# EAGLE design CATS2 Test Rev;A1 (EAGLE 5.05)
MFG: Tyco; SOCKET_MFG: Mill-Max Mfg

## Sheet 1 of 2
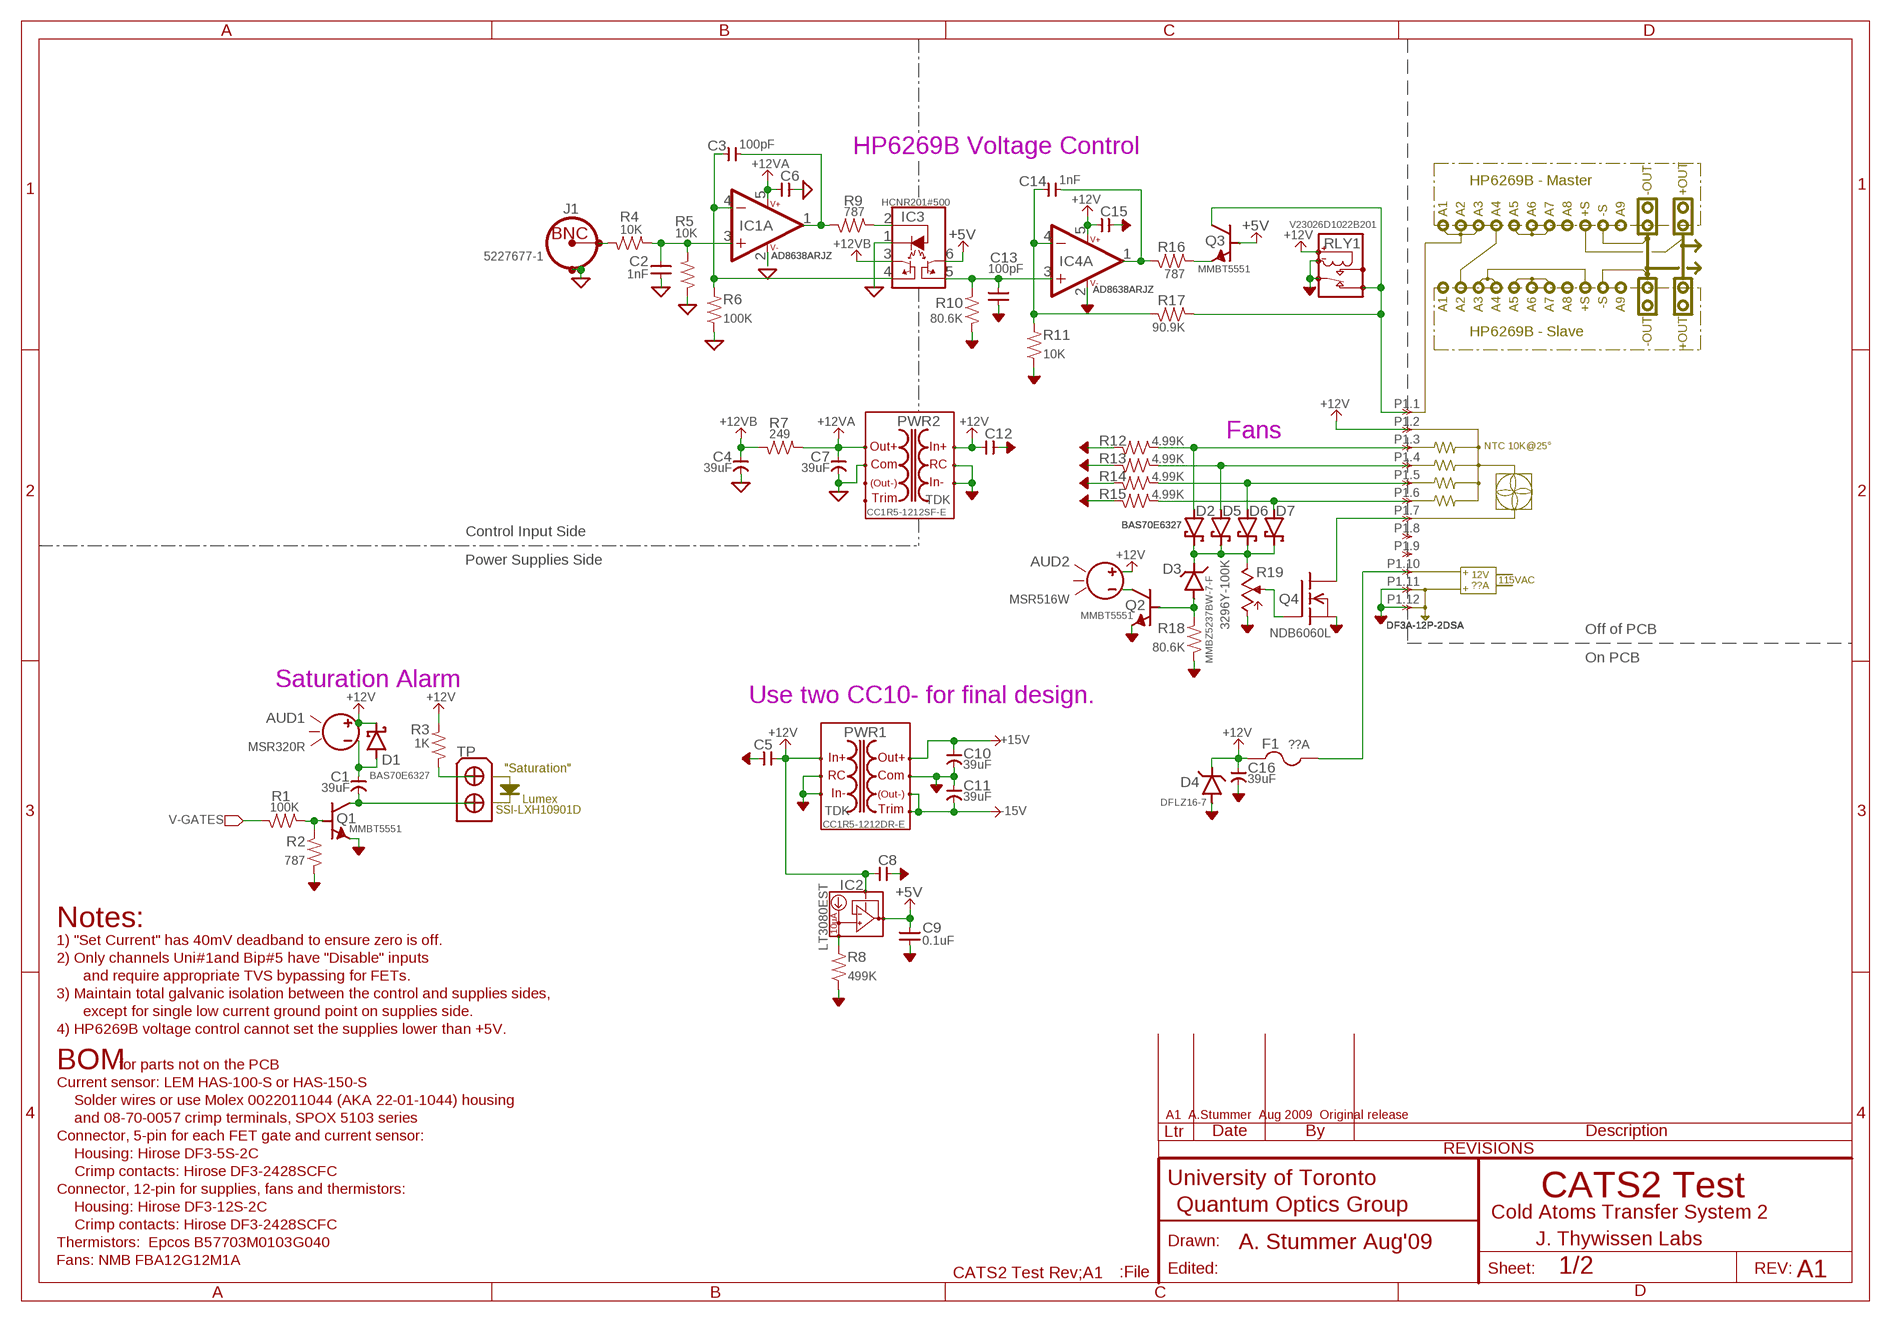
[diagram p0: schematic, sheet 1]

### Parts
AUD1  MSR320R  AUDIO_DEVICE1-MALLORY_MSR  [MALLORY_MSR]
AUD2  MSR516W  AUDIO_DEVICE1-MALLORY_MSR  [MALLORY_MSR]
C1  39uF  CAP-POL--NIPPONCHEM_E61  [CAP:NIPPONCHEM_E61]
C2  1nF  CAP-V-0805  [2012(0805)]
C3  100pF  CAP-H-0805  [2012(0805)]
C4  39uF  CAP-POL--NIPPONCHEM_E61  [CAP:NIPPONCHEM_E61]
C5  0.1uF  CAP-H-0805  [2012(0805)]
C6  0.1uF  CAP-H-0805  [2012(0805)]
C7  39uF  CAP-POL--NIPPONCHEM_E61  [CAP:NIPPONCHEM_E61]
C8  0.1uF  CAP-H-0805  [2012(0805)]
C9  0.1uF  CAP-V-0805  [2012(0805)]
C10  39uF  CAP-POL--NIPPONCHEM_E61  [CAP:NIPPONCHEM_E61]
C11  39uF  CAP-POL--NIPPONCHEM_E61  [CAP:NIPPONCHEM_E61]
C12  0.1uF  CAP-H-0805  [2012(0805)]
C13  100pF  CAP-V-0805  [2012(0805)]
C14  1nF  CAP-H-0805  [2012(0805)]
C15  0.1uF  CAP-H-0805  [2012(0805)]
C16  39uF  CAP-POL--NIPPONCHEM_E61  [CAP:NIPPONCHEM_E61]
D1  BAS70E6327  DIODE,SCHOTTKY-SOT-23  [SOT23]
D2  BAS70E6327  DIODE,SCHOTTKY-SOT-23  [SOT23]
D3  MMBZ5237BW-7-F  ZENER-SOT23  [SOT23]
D4  DFLZ16-7  ZENER-DFLZ  [ZENER:DFLZ_V_(1W)]
D5  BAS70E6327  DIODE,SCHOTTKY-SOT-23  [SOT23]
D6  BAS70E6327  DIODE,SCHOTTKY-SOT-23  [SOT23]
D7  BAS70E6327  DIODE,SCHOTTKY-SOT-23  [SOT23]
F1  ??A  FUSE-5X20-4  [FUSE]
IC1  AD8638ARJZ  OPAMP-SOT23-5  [SOT23-5]
IC2  LT3080EST  REGULATOR:LT3080(3PIN,LDO,I-SET)-SOT223  [SOT223(C)]
IC3  HCNR201#500  OPTO:LINEAR-TYPE1AVAGO#300  [SMD:AVAGO#300(8PIN)]
IC4  AD8638ARJZ  OPAMP-SOT23-5  [SOT23-5]
J1  5227677-1  CONN-BNCTYPE3HORIZ  [CONN-BNC-AMP-TYPE3HORIZ]
P1  DF3A-12P-2DSA  CONN-1X12-TYPE1  [CONN-1X12-TYPE1]
PWR1  CC1R5-1212DR-E  DC-DC:CCP-__-E(TDK1.5-25W)-CC1R5-R-E  [DC-DC:CC1R5-XXXXX-R-E(TDK/LAMBDA)]
PWR2  CC1R5-1212SF-E  DC-DC:CCP-__-E(TDK1.5-25W)-CC1R5-R-E  [DC-DC:CC1R5-XXXXX-R-E(TDK/LAMBDA)]
Q1  MMBT5551  BJT-NPN-SOT23  [SOT23]
Q2  MMBT5551  BJT-NPN-SOT23  [SOT23]
Q3  MMBT5551  BJT-NPN-SOT23  [SOT23]
Q4  NDB6060L  FET-N:NDB6060L(6A,48V,LOGIC)  [TO263]
R1  100K  R-H-0805  [2012(0805)]
R2  787  R-V-0805  [2012(0805)]
R3  1K  R-V-0805  [2012(0805)]
R4  10K  R-H-0805  [2012(0805)]
R5  10K  R-V-0805  [2012(0805)]
R6  100K  R-V-0805  [2012(0805)]
R7  249  R-H-0805  [2012(0805)]
R8  499K  R-V-0805  [2012(0805)]
R9  787  R-H-0805  [2012(0805)]
R10  80.6K  R-V-0805  [2012(0805)]
R11  10K  R-V-0805  [2012(0805)]
R12  4.99K  R-H-0805  [2012(0805)]
R13  4.99K  R-H-0805  [2012(0805)]
R14  4.99K  R-H-0805  [2012(0805)]
R15  4.99K  R-H-0805  [2012(0805)]
R16  787  R-H-0805  [2012(0805)]
R17  90.9K  R-H-0805  [2012(0805)]
R18  80.6K  R-V-0805  [2012(0805)]
R19  3296Y-100K  POT-BOURNS_3296Y  [BOURNS-3296Y]
RLY1  V23026D1022B201  RELAY:SPDT-TYCO_V23026(SMT)  [RELAY:SPDT-TYCO_V23026]
TP  CONN-TP2-1X2  [JUMPER-1X2]

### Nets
+5V: C9.2 IC2.2(OUT) IC3.6(VCC2) Q3.1(B) ; also sheet 2
+12V: AUD1.+ AUD2.+ C5.1 C8.1 C12.1 C15.1 C16.POS D1.3(C) D4.C F1.1A IC2.3(IN) IC4.5(B:V++) P1.2 PWR1.+VIN(+IN) PWR2.+VIN(+IN) R3.2 RLY1.COIL+ ; also sheet 2
+12VA: C6.1 C7.POS IC1.5(B:V++) PWR2.+VOUT(+OUT) R7.1 ; also sheet 2
+12VB: C4.POS IC3.3(VCC1) R7.2 ; also sheet 2
+15V: C10.POS PWR1.+VOUT(+OUT) ; also sheet 2
-15V: C11.NEG PWR1.-VOUT(-OUT) PWR1.TRM(TRIM) ; also sheet 2
AGND: C5.2 C8.2 C9.1 C10.NEG C11.POS C12.2 C13.1 C15.2 C16.NEG D4.A IC4.2(B:V-) P1.11 P1.12 PWR1.-VIN(-IN) PWR1.COM PWR1.RC PWR2.-VIN(-IN) PWR2.RC Q1.2(E) Q2.2(E) Q4.3(S) R2.1 R8.1 R10.1 R11.1 R12.2 R13.2 R14.2 R15.2 R18.1 R19.CCW RLY1.COIL- RLY1.COM ; also sheet 2
GND: C2.1 C4.NEG C6.2 C7.NEG IC1.2(B:V-) IC3.1(LED-) J1.SHIELD1 J1.SHIELD2 PWR2.COM R5.1 R6.1 ; also sheet 2
N$1: Q3.2(E) R16.1
N$2: C14.2 IC4.1(A:OUT) R16.2
N$4: C14.1 IC4.4(A:-IN) R11.2 R17.2
N$19: R3.1 TP.1
N$20: P1.1 Q3.3(C) R17.1 RLY1.NC
N$24: Q1.1(B) R1.1 R2.2
N$27: C1.NEG Q1.3(C) TP.2
N$28: AUD1.- C1.POS D1.1(A)
N$29: D3.1(A) Q2.1(B) R18.2
N$30: IC2.1(SET) R8.2
N$31: F1.2A P1.10
N$32: P1.7 Q4.2(D)
N$33: D7.1(A) P1.6 R15.1
N$34: D6.1(A) P1.5 R14.1
N$35: D5.1(A) P1.4 R13.1
N$36: D2.1(A) P1.3 R12.1
N$37: D2.3(C) D3.3(C) D5.3(C) D6.3(C) D7.3(C) R19.CW
N$38: Q4.1(G) R19.W
N$41: AUD2.- Q2.3(C)
N$49: C13.2 IC3.5(I2) IC4.3(A:+IN) R10.2
N$50: C3.2 IC1.1(A:OUT) R9.2
N$51: IC3.2(LED+) R9.1
N$52: J1.CONDUCTOR R4.2
N$53: C2.2 IC1.3(A:+IN) R4.1 R5.2
N$54: C3.1 IC1.4(A:-IN) IC3.4(I1) R6.2
V-GATES: R1.2 ; also sheet 2
Unconnected: P1.8 P1.9 PWR2.-VOUT(-OUT) PWR2.TRM(TRIM) RLY1.NO

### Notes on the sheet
- HP6269B Voltage Control
- HP6269B - Master
- -OUT | +OUT
- A1 | A2 | A3 | A4 | A5 | A6 | A7 | A8 | +S | -S | A9
- A1 | A2 | A3 | A4 | A5 | A6 | A7 | A8 | +S | -S | A9
- -OUT | +OUT
- HP6269B - Slave
- Fans
- NTC 10K@25°
- Control Input Side
- Power Supplies Side
- + | 12V
- 115VAC
- ??A
- +
- Off of PCB
- On PCB
- Saturation Alarm
- Use two CC10- for final design.
- "Saturation"
- Lumex
- SSI-LXH10901D
- Notes:
- 1) "Set Current" has 40mV deadband to ensure zero is off.
- 2) Only channels Uni#1and Bip#5 have "Disable" inputs
- and require appropriate TVS bypassing for FETs.
- 3) Maintain total galvanic isolation between the control and supplies sides,
- except for single low current ground point on supplies side.
- 4) HP6269B voltage control cannot set the supplies lower than +5V.
- BOM | for parts not on the PCB
- Current sensor: LEM HAS-100-S or HAS-150-S
- Solder wires or use Molex 0022011044 (AKA 22-01-1044) housing
- A1  A.Stummer  Aug 2009  Original release
- and 08-70-0057 crimp terminals, SPOX 5103 series
- Connector, 5-pin for each FET gate and current sensor:
- Housing: Hirose DF3-5S-2C
- Crimp contacts: Hirose DF3-2428SCFC
- Connector, 12-pin for supplies, fans and thermistors: | CATS2 Test
- Housing: Hirose DF3-12S-2C
- Cold Atoms Transfer System 2
- Crimp contacts: Hirose DF3-2428SCFC
- Thermistors:  Epcos B57703M0103G040 | A. Stummer Aug'09 | J. Thywissen Labs
- Fans: NMB FBA12G12M1A
- A1

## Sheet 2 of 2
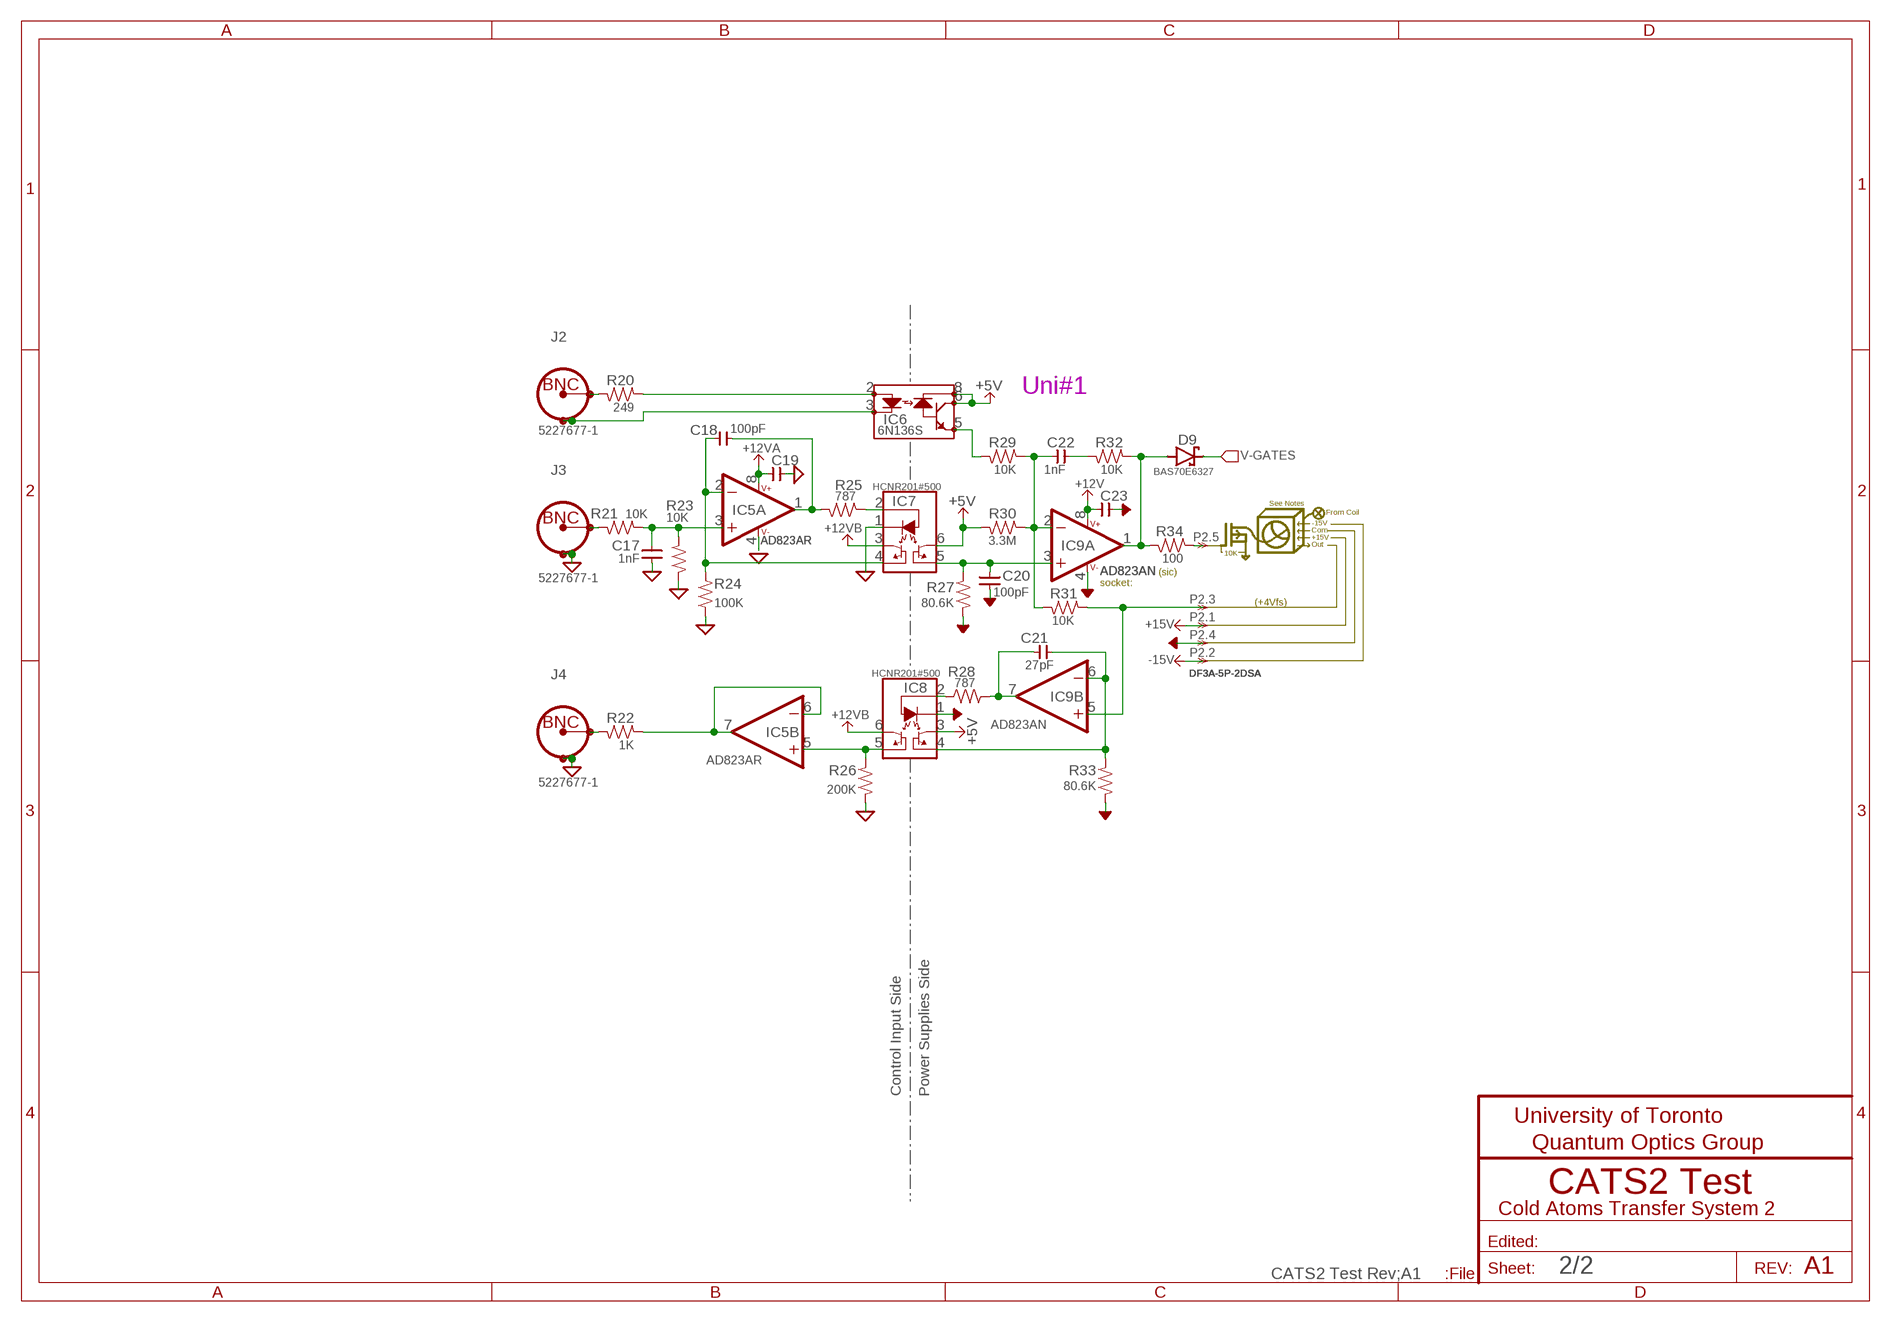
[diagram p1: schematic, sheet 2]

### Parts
C17  1nF  CAP-V-0805  [2012(0805)]
C18  100pF  CAP-H-0805  [2012(0805)]
C19  0.1uF  CAP-H-0805  [2012(0805)]
C20  100pF  CAP-V-0805  [2012(0805)]
C21  27pF  CAP-H-0805  [2012(0805)]
C22  1nF  CAP-H-0805  [2012(0805)]
C23  0.1uF  CAP-H-0805  [2012(0805)]
D9  BAS70E6327  DIODE,SCHOTTKY-SOT-23  [SOT23]
IC5  AD823AR  OPAMP:AD8___(DUAL)-SOIC-8  [SOIC-8]
IC6  6N136S  OPTO:6N136-S  [SMD:6N13X(8PIN)]
IC7  HCNR201#500  OPTO:LINEAR-TYPE1AVAGO#300  [SMD:AVAGO#300(8PIN)]
IC8  HCNR201#500  OPTO:LINEAR-TYPE1AVAGO#300  [SMD:AVAGO#300(8PIN)]
IC9  AD823AN  OPAMP:AD8___(DUAL)-DIP8  [DIL08]
J2  5227677-1  CONN-BNCTYPE3HORIZ  [CONN-BNC-AMP-TYPE3HORIZ]
J3  5227677-1  CONN-BNCTYPE3HORIZ  [CONN-BNC-AMP-TYPE3HORIZ]
J4  5227677-1  CONN-BNCTYPE3HORIZ  [CONN-BNC-AMP-TYPE3HORIZ]
P2  DF3A-5P-2DSA  CONN-1X5-TYPE1  [CONN-1X5-TYPE1]
R20  249  R-H-0805  [2012(0805)]
R21  10K  R-H-0805  [2012(0805)]
R22  1K  R-H-0805  [2012(0805)]
R23  10K  R-V-0805  [2012(0805)]
R24  100K  R-V-0805  [2012(0805)]
R25  787  R-H-0805  [2012(0805)]
R26  200K  R-V-0805  [2012(0805)]
R27  80.6K  R-V-0805  [2012(0805)]
R28  787  R-H-0805  [2012(0805)]
R29  10K  R-H-0805  [2012(0805)]
R30  3.3M  R-H-0805  [2012(0805)]
R31  10K  R-H-0805  [2012(0805)]
R32  10K  R-H-0805  [2012(0805)]
R33  80.6K  R-V-0805  [2012(0805)]
R34  100  R-H-0805  [2012(0805)]

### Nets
+5V: IC6.6(OUT) IC6.8(VDD) IC7.6(VCC2) IC8.3(VCC1) R30.2 ; also sheet 1
+12V: C23.1 IC9.8(PWR:V++) ; also sheet 1
+12VA: C19.1 IC5.8(PWR:V++) ; also sheet 1
+12VB: IC7.3(VCC1) IC8.6(VCC2) ; also sheet 1
+15V: P2.1 ; also sheet 1
-15V: P2.2 ; also sheet 1
AGND: C20.1 C23.2 IC8.1(LED-) IC9.4(PWR:V-) P2.4 R27.1 R33.1 ; also sheet 1
GND: C17.1 C19.2 IC5.4(PWR:V-) IC7.1(LED-) J3.SHIELD1 J3.SHIELD2 J4.SHIELD1 J4.SHIELD2 R23.1 R24.1 R26.1 ; also sheet 1
N$43: P2.5 R34.1
N$44: D9.1(A) IC9.1(A:OUT) R32.1 R34.2
N$45: C22.1 IC9.2(A:-IN) R29.1 R30.1 R31.2
N$46: IC9.5(B:+IN) P2.3 R31.1
N$47: C22.2 R32.2
N$48: C20.2 IC7.5(I2) IC9.3(A:+IN) R27.2
N$55: C18.2 IC5.1(A:OUT) R25.2
N$56: IC7.2(LED+) R25.1
N$57: J3.CONDUCTOR R21.2
N$58: C17.2 IC5.3(A:+IN) R21.1 R23.2
N$59: C18.1 IC5.2(A:-IN) IC7.4(I1) R24.2
N$61: C21.2 IC9.7(B:OUT) R28.2
N$62: IC8.2(LED+) R28.1
N$63: C21.1 IC8.4(I1) IC9.6(B:-IN) R33.2
N$64: IC5.5(B:+IN) IC8.5(I2) R26.2
N$65: IC5.6(B:-IN) IC5.7(B:OUT) R22.1
N$66: J4.CONDUCTOR R22.2
N$67: J2.CONDUCTOR R20.2
N$68: IC6.2(ANODE) R20.1
N$69: IC6.3(CATHODE) J2.SHIELD1 J2.SHIELD2
N$71: IC6.5(COM) R29.2
V-GATES: D9.3(C) ; also sheet 1

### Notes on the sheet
- Uni#1
- See Notes
- From Coil
- -15V
- Com
- +15V
- Out
- 10K
- (sic)
- socket:
- (+4Vfs)
- Control Input Side | Power Supplies Side
- CATS2 Test
- Cold Atoms Transfer System 2
- A1

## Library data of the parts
AUD1 AUD2 = QuantumOptics:AUDIO_DEVICE1: Audio Warning Device, Mallory MSR series, through hole, various sounds.
C1 C4 C7 C10 C11 C16 = QuantumOptics:CAP-POL-: Capacitor, Polarized, SMT 0805 and up, probably tantalum.
C2 C9 C13 C17 C20 = QuantumOptics:CAP-V-: Cap, SMT and Through-hole, 0402 and up.
C3 C5 C6 C8 C12 C14 C15 C18 C19 C21-C23 = QuantumOptics:CAP-H-: Cap, SMT and Through-hole, 0402 and up.
D1 D2 D5-D7 D9 = QuantumOptics:DIODE,SCHOTTKY: Schottky Diode, general purpose.
D3 D4 = QuantumOptics:ZENER: Zener
F1 = QuantumOptics:FUSE: Fuse
IC1 IC4 = QuantumOptics:OPAMP: Op Amp, generic, pick the right package. e.g. AD8605: SOT-23-5, RRIO, 10MHz, Ib = 1pA, Vio < 65uV, 2.7-5.5V.
IC2 = QuantumOptics:REGULATOR:LT3080(3PIN,LDO,I-SET): LT3080, LDO, output set by single resistor, nice part, LinTech, 1A, SOT223, MSOP8, TO220. http://cds.linear.com/docs/Datasheet/3080f.pdf
IC3 IC7 IC8 = QuantumOptics:OPTO:LINEAR-TYPE1: Linear opto-coupler, Avago HCNR20x or Clare LOC11x Best: http://www.avagotech.com/docs/AV02-0886EN Okay: http://www.clare.com/home/pdfs.nsf/www/LOC110.pdf/$file/LOC110.pdf
IC5 IC9 = QuantumOptics:OPAMP:AD8___(DUAL): AD8xxx, Analog Devices, dual opamp in SOIC-8 and MSOP-8, various versions available. AD8066, AD8656, etc. e.g. http://www.analog.com/UploadedFiles/Data_Sheets/476080131AD8655_6_a.pdf
IC6 = QuantumOptics:OPTO:6N136: 6N136 optocoupler, Fairchild et al, 1Mbps CTR=27%typ, http://www.fairchildsemi.com/ds/6N/6N136.pdf, Can drop-in 6N137 with 10Mbps logic - http://www.fairchildsemi.com/ds/6N/6N137.pdf
J1-J4 = QuantumOptics:CONN-BNC: BNC PCB, horizontal or vertical, e.g. Horiz: Amp (5)227677-1, nut 1-329631-2, shoulder washer 330620. The two shield connections allow the assembly on either side of the board. Vert isolated: 5227222-6, http://catalog.tycoelectronics.com/TE/bin/TE.Connect?C=1&M=BYPN&TCPN=5227222-6&RQPN=5227222-6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
P1 = QuantumOptics:CONN-1X12-TYPE1: Connector, 12-pin, PCB to wires, Hirose DF3A-12P-2DSA, 2mm. Mates with connector DF3-12S-2C and crimp pins DF3-2428SCFC. http://www.hirose.co.jp/cataloge_hp/e54300012.pdf
P2 = QuantumOptics:CONN-1X5-TYPE1: Connector, 4-pin, PCB to wires, Hirose DF3A-4P-2DSA, 2mm. Mates with connector DF3-4S-2C and crimp pins DF3-2428SCFC. http://www.hirose.co.jp/cataloge_hp/e54300012.pdf
PWR1 PWR2 = QuantumOptics:DC-DC:CCP-__-E(TDK1.5-25W): CCp-inoutsc-E, TDK DC-DC isolated, 1.5-25W, uni- or bipolar "p": 1.5, 3, 6, 10, 15, or 25W. "in": Input 05, 12, 24 or 48V. "out": Output 3.3, 5, 12, ±12 (or 24), ±15 (or30V). "s": Polarity single or dual. "c": Case horiz DIP, horiz SMD or vertical SIP. http://www.tdk.co.jp/tefe02/ea335_cc_e.pdf
Q1-Q3 = QuantumOptics:BJT-NPN: NPN BJT, generic, p/n defined by VALUE field. E.g. Fairchild MMBT5551 (abs max 160V, 600mA. hFE>80@10mA.
Q4 = QuantumOptics:FET-N:NDB6060L(6A,48V,LOGIC): NDB6060L, Fairchild et al., logic level, 6A 48V, TO-263. http://www.fairchildsemi.com/ds/ND/NDB6060L.pdf
R1 R4 R7 R9 R12-R17 R20-R22 R25 R28-R32 R34 = QuantumOptics:R-H-*: Resistor, SMT & Through-Hole, horizontal symbol
R2 R3 R5 R6 R8 R10 R11 R18 R23 R24 R26 R27 R33 = QuantumOptics:R-V-*: Resistor, SMT & Through-Hole, vertical symbol
R19 = QuantumOptics:POT: Pot, regular or trimpot
RLY1 = QuantumOptics:RELAY:SPDT: SPDT Relay
TP = QuantumOptics:CONN-TP2: Terminal Block, 2 post, generic two post terminal block.

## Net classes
2 100A: width 6.35 mm, clearance 0.381 mm

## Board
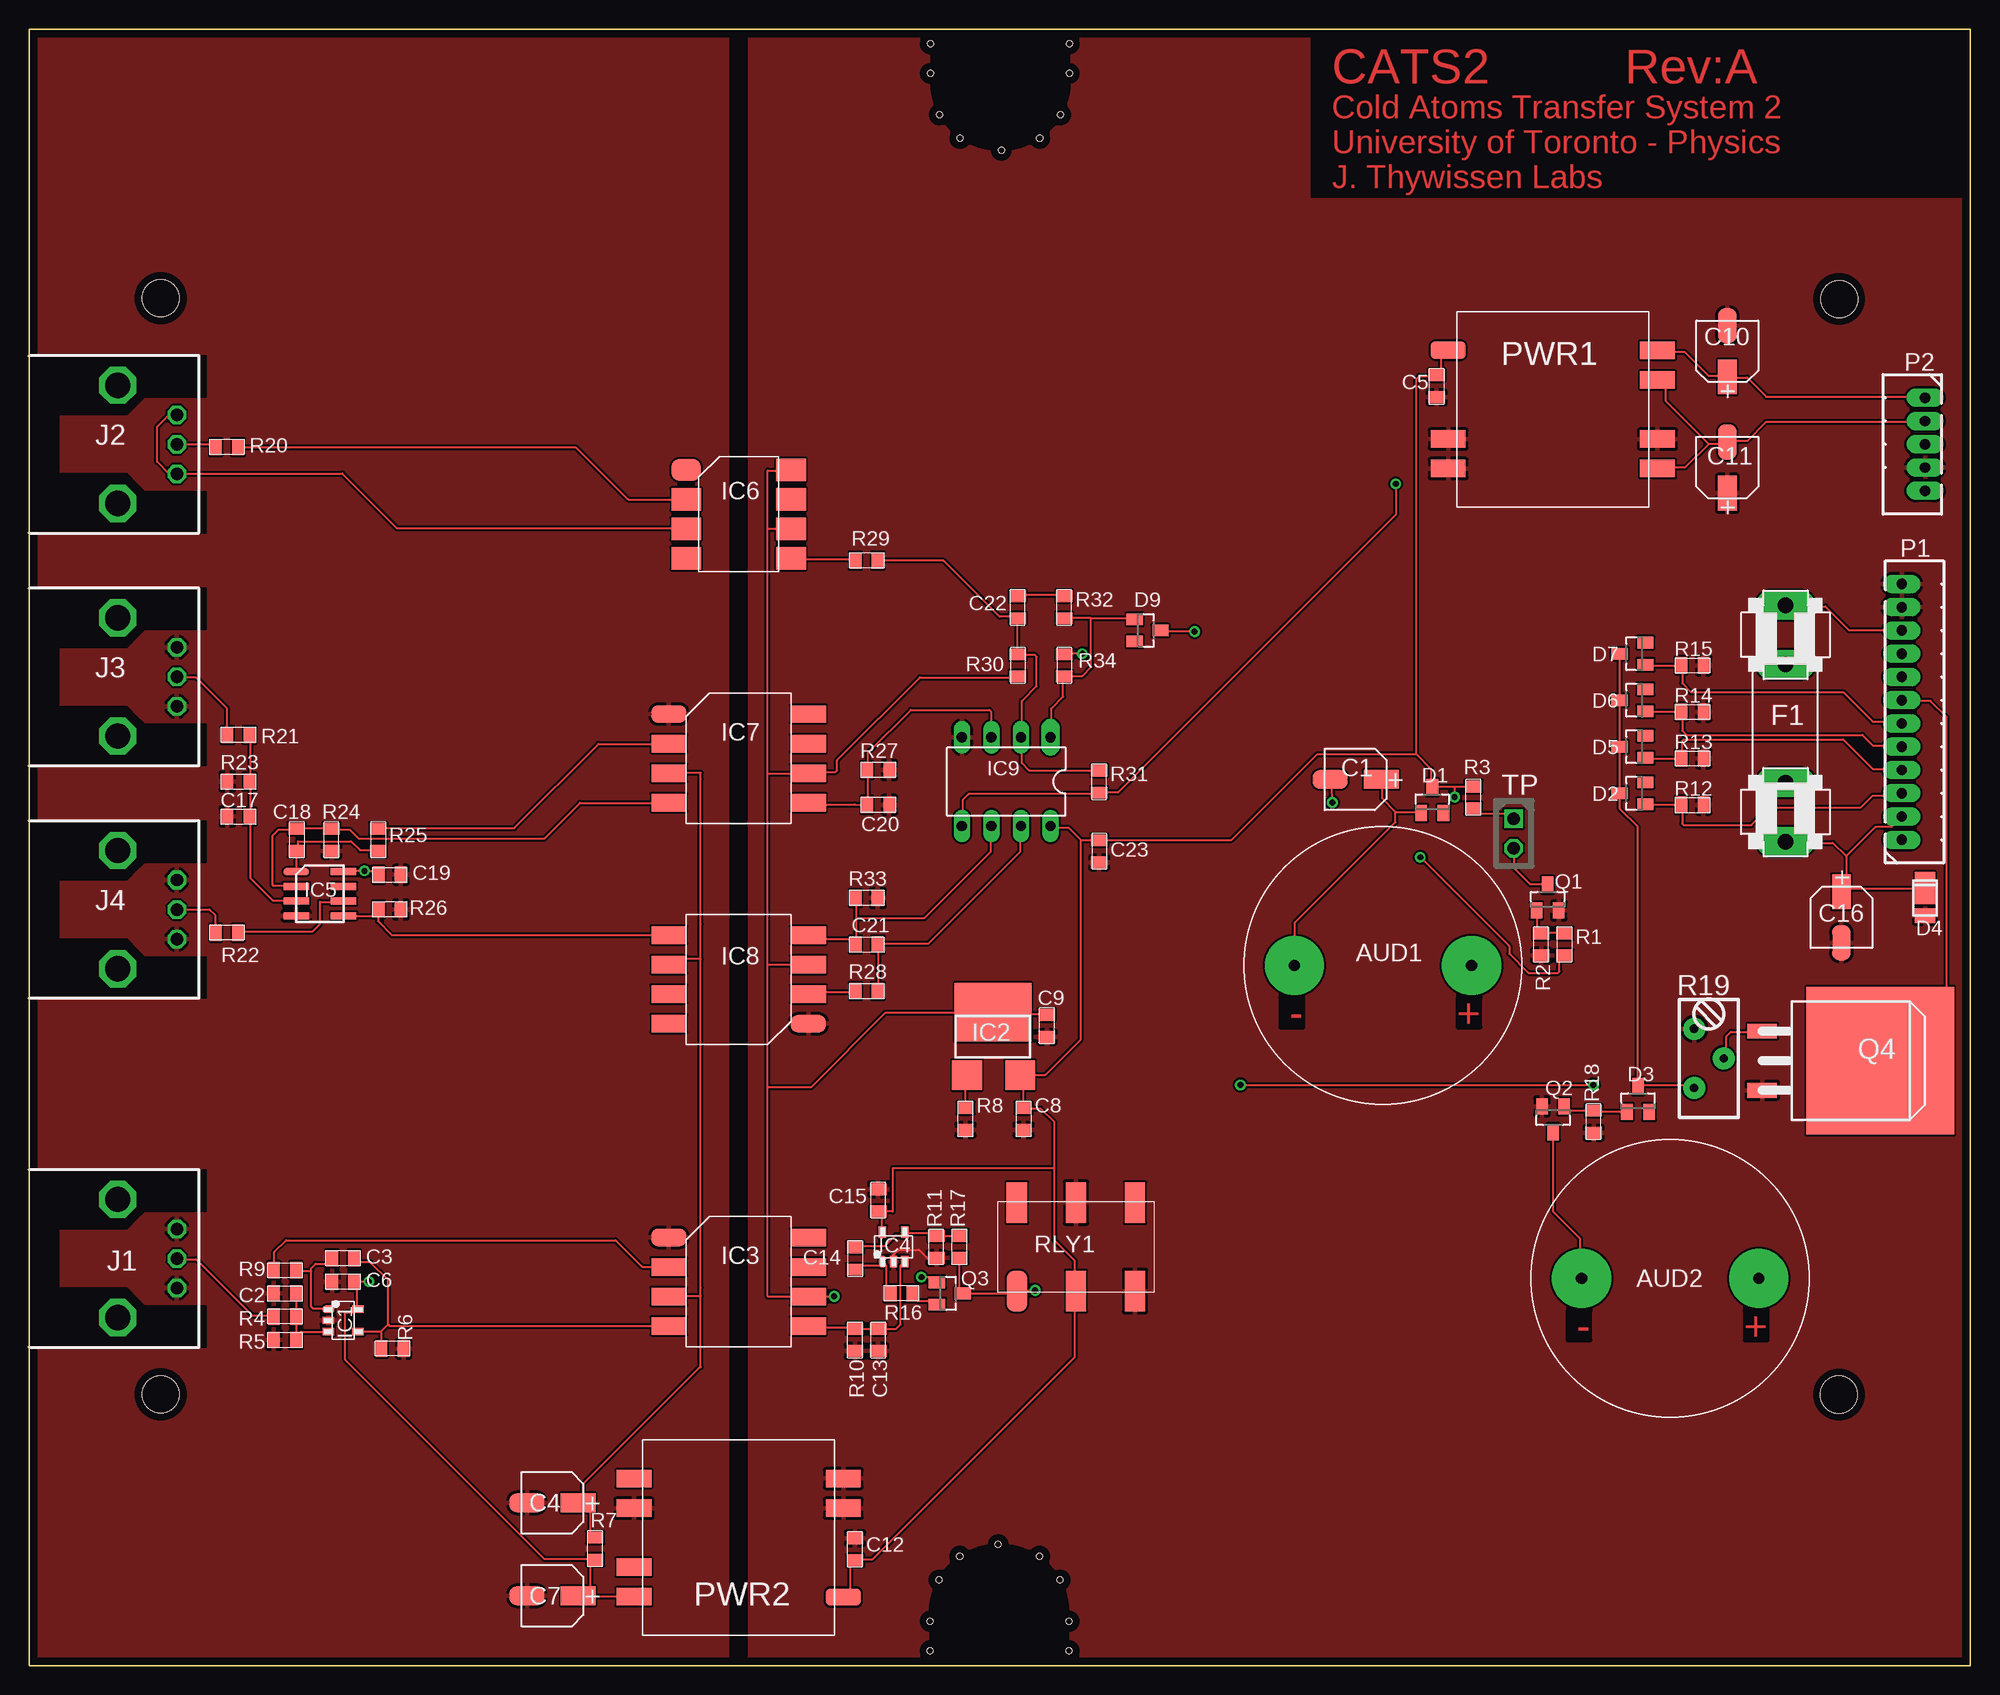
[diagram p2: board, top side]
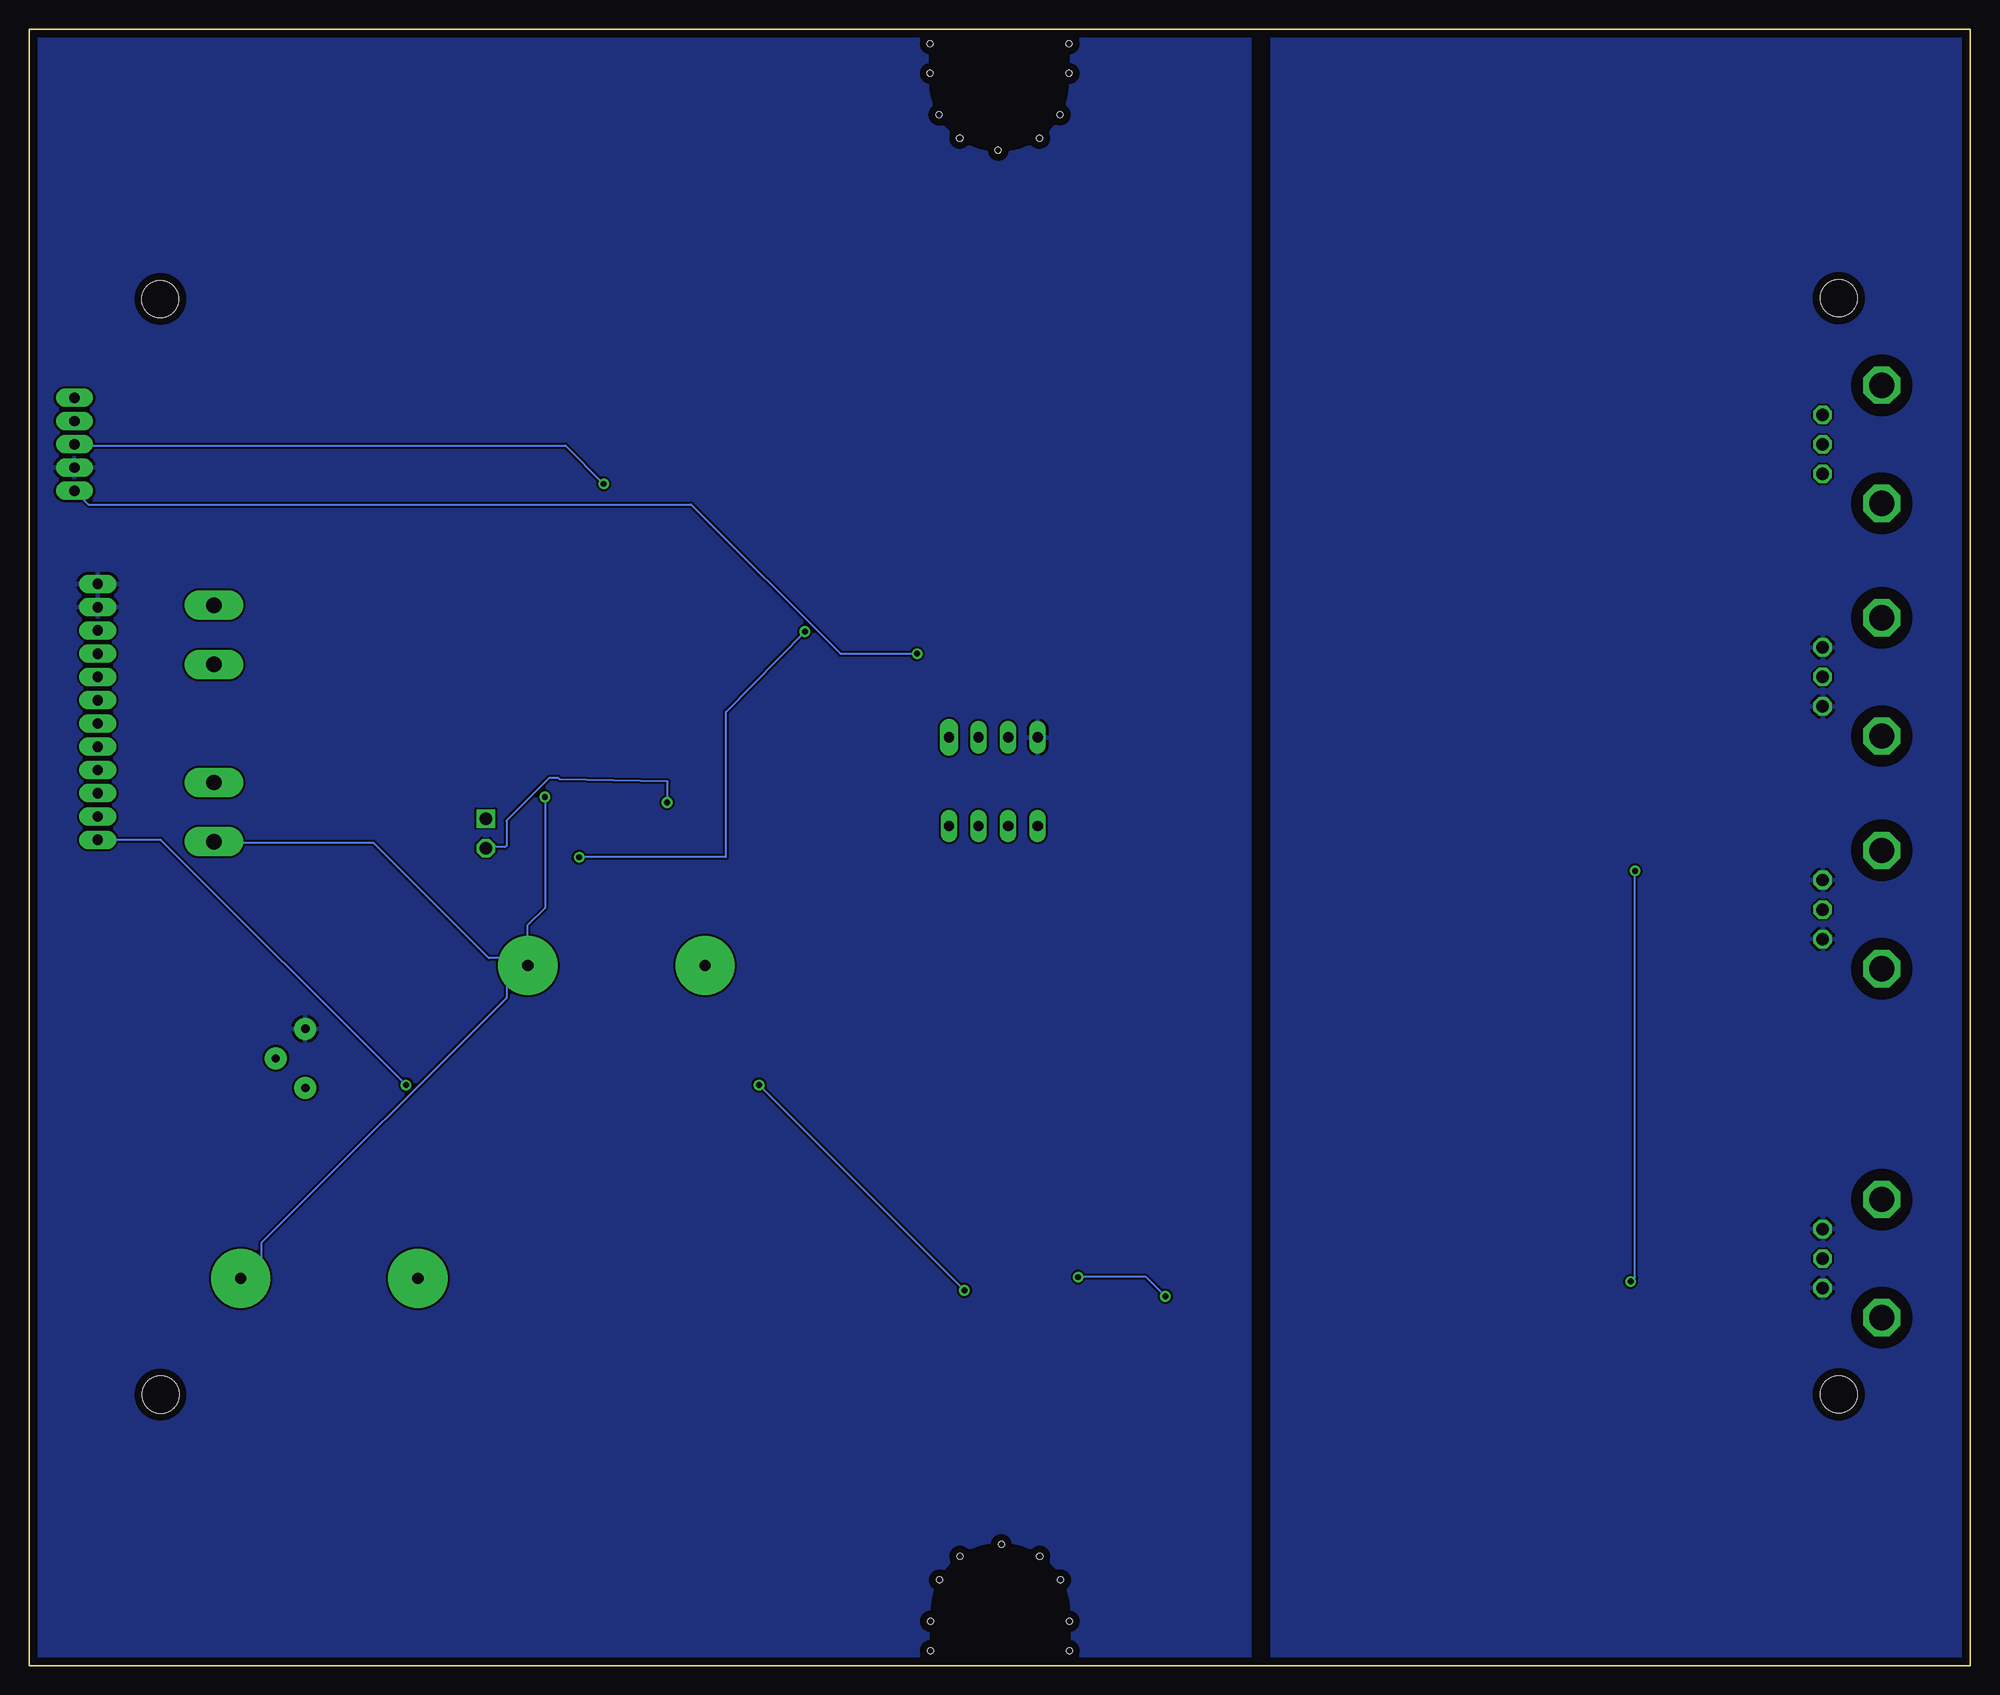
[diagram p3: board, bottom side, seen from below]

Size 166.9 x 140.7 mm. Coordinates in mm from the lower left corner, seen from the top.
Copper layers (1+16): Top 0.035mm / dielectric 1.5mm / Bottom 0.035mm
Design rules "DRC standard check": minimum track width 7mil, minimum drill 20mil, track to track 7mil, track to pad 7mil, pad to pad 7mil, via to via 7mil, smd to smd 0mil, copper to edge 25mil, drill to drill 8mil, minimum pad ring 10mil, minimum via ring 8mil, stop-mask expansion 4mil, vias tented up to drill 0mil, thermal gap 10mil
Holes 3.17 mm at 11.32,117.57 11.32,23.32 155.6,23.3 155.61,117.49

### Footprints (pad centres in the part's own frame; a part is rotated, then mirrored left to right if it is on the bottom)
MALLORY_MSR = drill 0.965 pad 5.08 round: + -7.62,0; - 7.62,0
CAP:NIPPONCHEM_E61 = smd 3 x 1.6: NEG -2.2,0; POS 2.2,0
2012(0805) = smd 1.016 x 1.397: 1 -0.953,0; 2 0.953,0
SOT23 = smd 1 x 1.4: 1 -0.953,-0.953; 2 0.953,-0.953; 3 0,1.27
ZENER:DFLZ_V_(1W) = smd 1.25 x 1.75: A -1.525,0 | smd 2.75 x 1.75: C 0.85,0
FUSE = drill 1.321 pad 2.54 long: 1A -10.16,0; 1B -5.08,0; 2A 10.16,0; 2B 5.08,0
SOT23-5 = smd 0.635 x 0.991: 1 -0.635,-1.27; 2 0.318,-1.27; 3 1.27,-1.27; 4 1.27,1.27; 5 -0.635,1.27
SOT223(C) = smd 2.54 x 2.54: 1 -2.286,-2.54; 3 2.286,-2.54 | smd 6.6 x 5: 2 -0.05,2.87
SMD:AVAGO#300(8PIN) = smd 1.5 x 3: 1 -3.81,-6; 2 -1.27,-6; 3 1.27,-6; 4 3.81,-6; 5 3.81,6; 6 1.27,6; 7 -1.27,6; 8 -3.81,6
SOIC-8 = smd 0.6 x 2.2: 1 -1.27,-2.032; 2 0,-2.032; 3 1.27,-2.032; 4 2.54,-2.032; 5 2.54,2.032; 6 1.27,2.032; 7 0,2.032; 8 -1.27,2.032
SMD:6N13X(8PIN) = smd 1.905 x 2.54: 1 -3.81,-4.508; 2 -1.27,-4.508; 3 1.27,-4.508; 4 3.81,-4.508; 5 3.81,4.508; 6 1.27,4.508; 7 -1.27,4.508; 8 -3.81,4.508
DIL08 = drill 0.889 pad 1.575 long: 1 -3.81,-3.81 | drill 0.889 long: 2 -1.27,-3.81; 3 1.27,-3.81; 4 3.81,-3.81; 5 3.81,3.81; 6 1.27,3.81; 7 -1.27,3.81; 8 -3.81,3.81
CONN-BNC-AMP-TYPE3HORIZ = drill 1.067 octagon: CONDUCTOR 0,-12.7; SHIELD1 -2.54,-12.7; SHIELD2 2.54,-12.7 | drill 2.184 octagon: P$1 -5.08,-7.62; P$2 5.08,-7.62
CONN-1X12-TYPE1 = drill 0.889 pad 1.6 long: 1 3,0; 2 1,0; 3 -1,0; 4 -3,0; 5 -5,0; 6 -7,0; 7 -9,0; 8 -11,0; 9 -13,0; 10 -15,0; 11 -17,0; 12 -19,0
CONN-1X5-TYPE1 = drill 0.889 pad 1.6 long: 1 3,0; 2 1,0; 3 -1,0; 4 -3,0; 5 -5,0
DC-DC:CC1R5-XXXXX-R-E(TDK/LAMBDA) = smd 3 x 1.5: +VIN -9,5.1; +VOUT 9,5.08; -VIN -9,-5.08; -VOUT 9,-5.08; COM 9,-2.54; RC -9,-2.54; TRM 9,2.54
TO263 = smd 1.27 x 2.54: 1 -2.54,0; 3 2.54,0 | smd 12.7 x 12.7: 2 0,10.16
BOURNS-3296Y = drill 0.711 pad 1.905 round: CCW 2.54,1.27; CW -2.54,1.27; W 0,-1.27
RELAY:SPDT-TYCO_V23026 = smd 1.75 x 3.5: 6 5.08,3.81; COIL+ 0,-3.81; COIL- 0,3.81; COM 5.08,-3.81; NC -5.08,-3.81; NO -5.08,3.81
JUMPER-1X2 = drill 1.067 square: 1 0,2.54 | drill 1.067 octagon: 2 0,0
CASE-HAMMOND-1598C = hole 0.508: 77.47,1.27; 77.47,3.81; 78.232,7.366; 80.01,9.398; 83.312,10.414; 86.868,9.398; 88.646,7.366; 89.408,3.81; 89.408,1.27; 89.43,139.43; 89.43,136.89; 88.668,133.334; 86.89,131.302; 83.588,130.286; 80.032,131.302; 78.254,133.334; 77.492,136.89; 77.492,139.43

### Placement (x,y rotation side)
AUD1  116.4,60.2 180 top
AUD2  141.09,33.3 180 top
C1  114.05,76.19 0 top
C2  22,32 0 top
C3  27,35 180 top
C4  45,14 0 top
C5  121,110 270 top
C6  27,33 180 top
C7  45,6 0 top
C8  85.5,47 270 top
C9  87.5,55 90 top
C10  146,113 270 top
C11  146,103 270 top
C12  71,10 90 top
C13  73,28 90 top
C14  71,35 270 top
C15  73,40 90 top
C16  155.81,64.33 90 top
C17  18,73 0 top
C18  23,71 270 top
C19  31,68 0 top
C20  73,74 180 top
C21  72,62 0 top
C22  85,91 90 top
C23  92,70 270 top
D1  120.64,74.25 0 top
D2  138,75 90 top
D3  138.32,48.55 0 top
D4  163,66 90 top
D5  138,79 90 top
D6  138,83 90 top
D7  138,87 90 top
D9  96,89 270 top
F1  151,81 90 top
IC1  27,30 270 top
IC2  82.92,53.31 0 top
IC3  61,33 270 top
IC4  74,36 0 top
IC5  25,67 270 top
IC6  61,99 270 top
IC7  61,78 270 top
IC8  61,59 90 top
IC9  84,76 180 top
J1  0,35 90 top
J2  0,105 90 top
J3  0,85 90 top
J4  0,65 90 top
P1  161,74 270 top
P2  163,106 90 top
PWR1  131,108 0 top
PWR2  61,11 180 top
Q1  130.55,65.87 0 top
Q2  131.02,47.13 180 top
Q3  79,32 270 top
Q4  149,52 270 top
R1  132,62 270 top
R2  130,62 90 top
R3  124.16,74.64 90 top
R4  22,30 180 top
R5  22,28 0 top
R6  31.25,27.25 180 top
R7  48.66,10.06 90 top
R8  80.5,47 90 top
R9  22,34 0 top
R10  71,28 90 top
R11  78,36 90 top
R12  143,74 0 top
R13  143,78 0 top
R14  143,82 0 top
R15  143,86 0 top
R16  75,32 180 top
R17  80,36 90 top
R18  134.51,46.76 90 top
R19  144.42,52.21 90 top
R20  17,104.75 180 top
R21  18,80 180 top
R22  17,63 180 top
R23  18,76 0 top
R24  26,71 90 top
R25  30,71 270 top
R26  31,65 180 top
R27  73,77 180 top
R28  72,58 0 top
R29  72,95 180 top
R30  85,86 270 top
R31  92,76 90 top
R32  89,91 90 top
R33  72,66 180 top
R34  89,86 270 top
RLY1  90,36 0 top
TP  127.63,70.28 0 top
U$7  [CASE-HAMMOND-1598C]  0,0 0 top
U$8  [TITLEBLOCK_PCB]  not placed on the board

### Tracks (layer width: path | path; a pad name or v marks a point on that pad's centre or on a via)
+5V  (via drill 0.51)
  Top 0.178: C9.2 87.38,56.01 83.06,56.01 82.93,56.13 IC2.2 82.8,56.13 | v76.71,33.4 77.6,33.4 77.98,33.02 Q3.1 | v69.22,31.75 67.06,31.75 IC3.6 | IC6.6 65.53,97.79 | 65.53,102.74 IC6.8 | R30.2 84.96,84.96 76.58,84.96 69.47,77.85 69.47,76.96 69.34,76.83 67.06,76.83 IC7.6 66.93,76.71
  Top 0.18: 65.53,102.74 63.5,102.74 63.5,97.75 | 63.5,76.71 66.93,76.71 | 63.5,76.71 63.5,97.75 | 63.5,97.75 65.51,97.75 IC6.6 | 63.5,60.27 IC8.3 | 63.5,60.27 63.5,76.71 | IC3.6 63.5,31.73 63.5,49.75 | 63.5,49.75 63.5,60.27 | 82.8,56.13 73.63,56.13 67.25,49.75 63.5,49.75
  Bottom 0.178: v76.71,33.4 70.87,33.4 v69.22,31.75
+12V  (via drill 0.51)
  Top 0.178: 90.42,70.99 91.95,70.99 C23.1 92.08,70.99 103.38,70.99 110.74,78.36 119.25,78.36 | 90.42,70.99 89.41,72.01 88.01,72.01 87.88,72.14 IC9.8 | PWR2.+VIN 70.1,5.97 70.61,6.48 70.61,8.64 70.99,9.02 C12.1 71.12,9.14 72.52,9.14 89.92,26.54 89.92,32.13 RLY1.COIL+ 89.92,32.26 89.92,34.8 88.14,36.58 88.14,42.75 88.14,46.74 87,47.88 85.6,47.88 C8.1 85.47,48.01 85.47,50.42 85.22,50.67 IC2.3 85.22,50.8 87.38,50.8 90.42,53.85 90.42,70.99 | 156.21,66.8 156.08,66.8 155.83,66.55 C16.POS 156.21,66.8 | 156.21,66.8 162.94,66.8 D4.C | 156.21,69.6 158.75,72.14 160.15,72.14 160.91,72.9 P1.2 | 156.21,69.6 156.21,66.8 | 156.21,69.6 155.07,70.74 151,70.74 F1.1A | PWR1.+VIN 121.92,113.03 121.41,112.52 121.41,111.38 121.03,111 C5.1 120.9,110.87 119.51,110.87 119.25,110.62 119.25,78.36 | 122.56,75.56 120.65,75.56 D1.3 120.52,75.56 120.52,77.09 119.25,78.36 | 122.56,75.56 124.08,75.56 R3.2 | 122.56,75.56 v122.56,74.68 | IC4.5 73.28,37.34 73.28,38.73 73.03,38.99 C15.1
  Top 0.18: 88.14,42.75 74.25,42.75 74.25,39.05 C15.1
  Bottom 0.178: v122.56,74.68 122.56,65.15 124.08,63.63 124.08,60.83 | 124.08,60.83 124.08,60.33 AUD1.+ 124.08,60.83 | 124.08,60.83 125.86,60.83 | 125.86,60.83 127.38,60.83 137.29,70.74 150.88,70.74 F1.1A | 125.86,60.83 125.86,57.4 146.94,36.32 146.94,35.05 148.59,33.4 AUD2.+
+12VA  (via drill 0.51)
  Top 0.178: 52.07,5.97 PWR2.+VOUT 51.94,5.97 47.24,5.97 C7.POS 47.24,6.1 47.62,6.1 48.26,6.73 48.26,8.64 48.64,9.02 R7.1 48.64,9.14 44.32,9.14 27.18,26.29 27.18,30.35 27.81,30.35 28.07,30.61 28.19,30.61 IC1.5 28.19,30.73 28.19,32.77 28.07,32.89 C6.1 28.07,33.02 v29.21,33.02 | C19.1 29.97,68.07 29.72,68.33 v28.83,68.33 27.05,68.33 IC5.8
  Bottom 0.178: v28.83,68.33 28.83,33.4 v29.21,33.02
+12VB
  Top 0.178: 57.75,63.75 57.75,76.25 | 55.12,60.33 IC8.6 | 55.12,76.71 IC7.3 | 47.62,13.97 48.26,13.34 48.26,11.43 48.64,11.05 R7.2 | 47.62,13.97 47.24,13.97 C4.POS 47.62,13.97 | 57.66,25.65 47.62,15.62 47.62,13.97 | 55.12,31.62 IC3.3 | 57.75,32.5 57.75,60.75
  Top 0.18: 55.12,60.33 55.12,60.75 57.75,60.75 57.75,63.75 | 57.75,31.75 57.75,25.65 57.66,25.65 | 57.75,31.75 57.75,32.5 | 55.12,31.62 55.12,31.75 57.75,31.75 | 55.12,76.71 55.12,76.75 57.75,76.75 57.75,76.25
+15V
  Top 0.178: PWR1.+VOUT 140.08,113.03 140.21,112.9 142.37,112.9 144.4,110.87 145.92,110.87 C10.POS 146.05,110.74 147.7,110.74 149.35,109.09 162.94,109.09 P2.1
-15V
  Top 0.178: 144.4,105.03 142.37,103 140.08,103 PWR1.-VOUT | 144.4,105.03 145.8,105.03 145.92,105.16 C11.NEG 146.05,105.28 147.7,105.28 149.35,106.93 162.94,106.93 P2.2 | 144.4,105.03 140.72,108.71 140.72,109.86 140.08,110.49 PWR1.TRM
AGND
  Top 0.18: IC4.2 74.32,35.32 74.75,35.75 76.5,35.75 77.25,35 77.95,35 R11.1
  pour Top: 62,0 167,0 167,126 110,126 110,140 62,140
  pour Bottom: 62,0 167,0 167,140 62,140
GND
  pour Top: 0,140 60,140 60,0 0,0
  pour Bottom: 0,140 60,140 60,0 0,0
N$1
  Top 0.178: R16.1 76.07,31.88 76.07,31.62 76.33,31.37 77.72,31.37 77.98,31.11 Q3.2
N$2
  Top 0.178: 73.66,34.42 73.41,34.67 IC4.1 73.66,34.42 | 73.66,34.42 73.66,32.38 R16.2 | 73.66,34.42 71.63,34.42 71.37,34.16 71.12,34.16 C14.2
N$4
  Top 0.178: 72.93,36.07 71.12,36.07 C14.1 | 75.18,37.21 IC4.4 75.31,37.21 77.72,37.21 77.98,36.96 R11.2 78.11,36.96 79.88,36.96 R17.2
  Top 0.18: 72.93,36.07 73.57,36.07 74.5,37 75,37 IC4.4
N$19
  Top 0.178: R3.1 124.21,73.66 124.59,73.28 127.13,73.28 127.51,72.9 TP.1
N$20  (via drill 0.51)
  Top 0.178: R17.1 80.01,34.92 80.01,32.26 Q3.3 80.39,32 84.71,32 84.84,32.13 RLY1.NC 84.96,32.26 v86.49,32.26 | v104.14,49.91 v134.49,49.91
  Bottom 0.178: v134.49,49.91 155.57,70.99 160.91,70.99 P1.1 | v86.49,32.26 v104.14,49.91
N$24
  Top 0.178: R1.1 131.95,62.99 130.05,62.99 R2.2 129.92,62.99 129.67,63.25 129.67,64.9 Q1.1
N$27  (via drill 0.51)
  Top 0.178: Q1.3 130.43,67.18 129.03,67.18 127.64,68.58 127.64,70.23 TP.2 | v112.05,74.2 111.89,76.2 C1.NEG
  Bottom 0.178: v112.05,74.2 112,74.2 112,76 121.28,76.2 121.41,76.33 122.17,76.33 125.86,72.64 125.86,70.48 125.98,70.36 127.51,70.36 TP.2
N$28
  Top 0.178: 117.47,73.41 119.63,73.41 D1.1 | 117.47,73.41 116.33,74.55 116.33,76.07 C1.POS | 117.47,73.41 117.47,72.52 108.84,63.88 108.84,60.33 AUD1.-
N$29
  Top 0.178: D3.1 137.29,47.62 134.62,47.62 R18.2 134.49,47.75 132.33,47.75 132.08,48.01 Q2.1
N$30
  Top 0.178: R8.2 80.52,48.01 80.52,50.67 IC2.1
N$31
  Top 0.178: P1.10 160.91,89.03 156.46,89.03 154.43,91.06 151,91.06 F1.2A
N$32
  Top 0.178: P1.7 161.04,82.93 163.45,82.93 164.85,81.53 164.85,57.66 159.26,52.07 Q4.2
N$33
  Top 0.178: D7.1 139.06,85.98 141.99,85.98 R15.1 142.11,85.98 142.11,84.45 142.88,83.69 155.96,83.69 158.5,81.15 160.78,81.15 160.91,81.03 P1.6
N$34
  Top 0.178: D6.1 139.06,82.04 141.99,82.04 R14.1 142.11,81.92 142.11,80.39 142.49,80.01 157.61,80.01 158.5,79.12 160.91,79.12 P1.5
N$35
  Top 0.178: D5.1 139.06,77.98 141.99,77.98 R13.1 142.11,78.11 142.11,79.5 142.24,79.63 155.96,79.63 158.5,77.09 160.91,77.09 P1.4
N$36
  Top 0.178: D2.1 139.06,74.04 141.99,74.04 R12.1 142.11,73.91 142.11,72.39 142.24,72.26 148.08,72.26 149.61,73.79 157.48,73.79 158.5,74.8 160.78,74.8 160.91,74.93 P1.3
N$37
  Top 0.178: R19.CW 143.13,49.78 143,49.91 138.43,49.91 D3.3 138.3,49.91 138.3,72.14 136.78,73.66 136.78,74.93 D2.3 136.78,75.06 136.78,78.99 D5.3 136.78,79.12 136.78,82.93 D6.3 136.78,83.06 136.78,87 D7.3
N$38
  Top 0.178: Q4.1 148.97,54.48 146.3,54.48 145.92,54.1 145.92,52.45 145.8,52.32 R19.W
N$41
  Top 0.178: Q2.3 131.06,45.85 131.06,38.99 133.35,36.7 133.35,33.4 AUD2.-
N$43  (via drill 0.51)
  Top 0.178: v90.55,87 89.03,87 R34.1
  Bottom 0.178: v90.55,87 97.16,87 110,99.84 161.81,99.84 162.94,100.97 P2.5
N$44
  Top 0.178: 91.31,90.04 95,90.04 D9.1 | 91.31,90.04 89.03,90.04 R32.1 | IC9.1 87.88,79.88 87.88,82.3 88.9,83.31 88.9,84.96 R34.2 89.03,85.09 90.55,85.09 91.31,85.85 91.31,90.04
N$45
  Top 0.178: R31.2 91.95,76.96 85.98,76.96 85.34,77.6 85.34,79.76 IC9.2 85.34,79.88 85.34,82.93 86.61,84.2 86.61,86.74 86.49,86.87 85.09,86.87 R30.1 84.96,87 84.96,90.04 C22.1 84.96,90.17 83.44,90.17 78.61,95 73.03,95 R29.1
N$46  (via drill 0.51)
  Top 0.178: IC9.5 80.26,72.26 80.26,74.42 80.77,74.93 91.95,74.93 R31.1 92.08,75.06 93.6,75.06 117.49,98.95 v117.49,101.6
  Bottom 0.178: v117.49,101.6 120.79,104.9 162.94,104.9 P2.3
N$47
  Top 0.178: C22.2 85.09,92.08 88.9,92.08 R32.2
N$48
  Top 0.178: IC7.5 67.06,74.17 67.18,74.04 70.99,74.04 C20.2 72.12,74.04 72.12,76.96 R27.2 72.12,77.09 72.12,78.49 75.8,82.17 82.55,82.17 82.68,82.04 82.68,79.88 IC9.3
N$49
  Top 0.178: IC4.3 75.18,34.67 74.93,34.42 74.93,29.34 74.55,28.96 73.03,28.96 C13.2 72.9,28.96 71.12,28.96 R10.2 70.87,29.08 67.06,29.08 IC3.5
N$50
  Top 0.178: 24.26,33.91 24.26,30.86 24.38,30.73 25.65,30.73 IC1.1 | 24.26,33.91 22.99,33.91 R9.2 | 24.26,33.91 24.26,34.16 24.64,34.54 25.65,34.54 26.04,34.92 C3.2
N$51
  Top 0.178: R9.1 21.08,34.04 21.08,35.56 22.1,36.58 50.42,36.58 52.7,34.29 54.99,34.29 IC3.2
N$52
  Top 0.178: R4.2 20.95,30.1 19.18,30.1 14.35,34.92 12.7,34.92 J1.CONDUCTOR
N$53
  Top 0.178: 22.99,28.32 23.37,28.7 25.65,28.7 IC1.3 | 22.99,28.32 22.99,28.07 R5.2 22.99,28.32 | 22.99,28.32 22.99,29.97 R4.1 22.99,30.1 22.99,31.88 C2.2
N$54
  Top 0.178: 28.32,28.7 IC1.4 | 30.86,29.32 30.86,33.15 29.34,34.67 28.32,34.67 28.07,34.92 C3.1 | 54.99,29.21 IC3.4
  Top 0.18: 30.24,28.7 28.32,28.7 | 30.24,28.7 30.86,29.32 30.97,29.21 54.99,29.21 | R6.2 30.3,28.65 30.24,28.7
N$55
  Top 0.178: IC5.1 22.99,68.33 22.99,69.98 C18.2 23.11,70.1 23.11,70.87 27.69,70.87 28.45,70.1 29.97,70.1 R25.2
N$56
  Top 0.178: R25.1 30.1,72.01 41.7,72.01 48.94,79.25 54.99,79.25 IC7.2
N$57
  Top 0.178: R21.2 17.02,80.01 17.02,82.3 14.35,84.96 12.7,84.96 J3.CONDUCTOR
N$58
  Top 0.178: R21.1 19.05,79.88 19.05,76.07 R23.2 19.05,75.95 19.05,73.03 C17.2 19.05,72.9 19.05,67.69 20.95,65.79 22.86,65.79 IC5.3
N$59
  Top 0.178: IC5.2 22.86,67.06 20.95,67.06 20.95,71.37 21.46,71.88 22.99,71.88 C18.1 23.11,72.01 25.91,72.01 R24.2 26.04,71.88 27.56,71.88 28.32,71.12 44.32,71.12 47.37,74.17 54.99,74.17 IC7.4
N$61
  Top 0.178: R28.2 73.03,58.04 73.03,61.98 C21.2 73.03,62.1 77.34,62.1 85.22,69.98 85.22,72.14 IC9.7
N$62
  Top 0.178: R28.1 70.99,57.91 67.18,57.91 67.06,57.78 IC8.2
N$63
  Top 0.178: 71.12,64.26 71.12,65.91 R33.2 | 71.12,62.48 71.12,64.26 | 71.12,62.48 71.12,62.1 C21.1 71.12,62.48 | 71.12,62.48 67.31,62.48 67.06,62.74 IC8.4 | 71.12,64.26 76.96,64.26 82.68,69.98 82.68,72.14 IC9.6
N$64
  Top 0.178: IC5.5 27.05,64.39 | IC8.5 54.99,62.74
  Top 0.18: IC8.5 31.19,62.81 30,64 30,64.95 R26.2 29.51,64.46 IC5.5
N$65
  Top 0.178: IC5.7 27.05,66.93 27.05,65.79 IC5.6 26.92,65.66 25.02,65.66 25.02,63.75 24.38,63.12 18.03,63.12 R22.1
N$66
  Top 0.178: R22.2 16,63.12 16,64.52 15.49,65.02 12.7,65.02 J4.CONDUCTOR
N$67
  Top 0.18: J2.CONDUCTOR 15.8,105 R20.2
N$68
  Top 0.178: 56.39,100.2 56.26,100.08 IC6.2 56.39,100.2
  Top 0.18: R20.1 47,104.75 51.5,100.25 56.47,100.25 IC6.2
N$69
  Top 0.178: IC6.3 56.39,97.79 31.62,97.79 26.92,102.49 12.7,102.49 J2.SHIELD1
  Top 0.18: J2.SHIELD2 12.04,107.54 11,106.5 11,103.5 12,102.5 12.66,102.5 J2.SHIELD1
N$71
  Top 0.178: R29.2 70.99,95.12 65.53,95.12 IC6.5
V-GATES  (via drill 0.51)
  Top 0.178: v119.6,69.5 127.25,61.85 127.25,61.21 128.91,59.56 131.44,59.56 131.57,59.69 131.57,60.58 131.95,60.96 R1.2 | v100.2,88.9 97.28,88.9 D9.3
  Bottom 0.178: v100.2,88.9 107,82 107,69.5 v119.6,69.5

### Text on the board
Top: CATS2 Rev:A | Cold Atoms Transfer System 2 | University of Toronto - Physics | J. Thywissen Labs
Reference: CATS2 Test | Cold Atoms Transfer System | A. Stummer Sept 2009 | A | 0.18mm | 0.18mm | 0.18mm | 1mm | 0.127mm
